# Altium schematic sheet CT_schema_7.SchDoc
size 277 x 170 mm
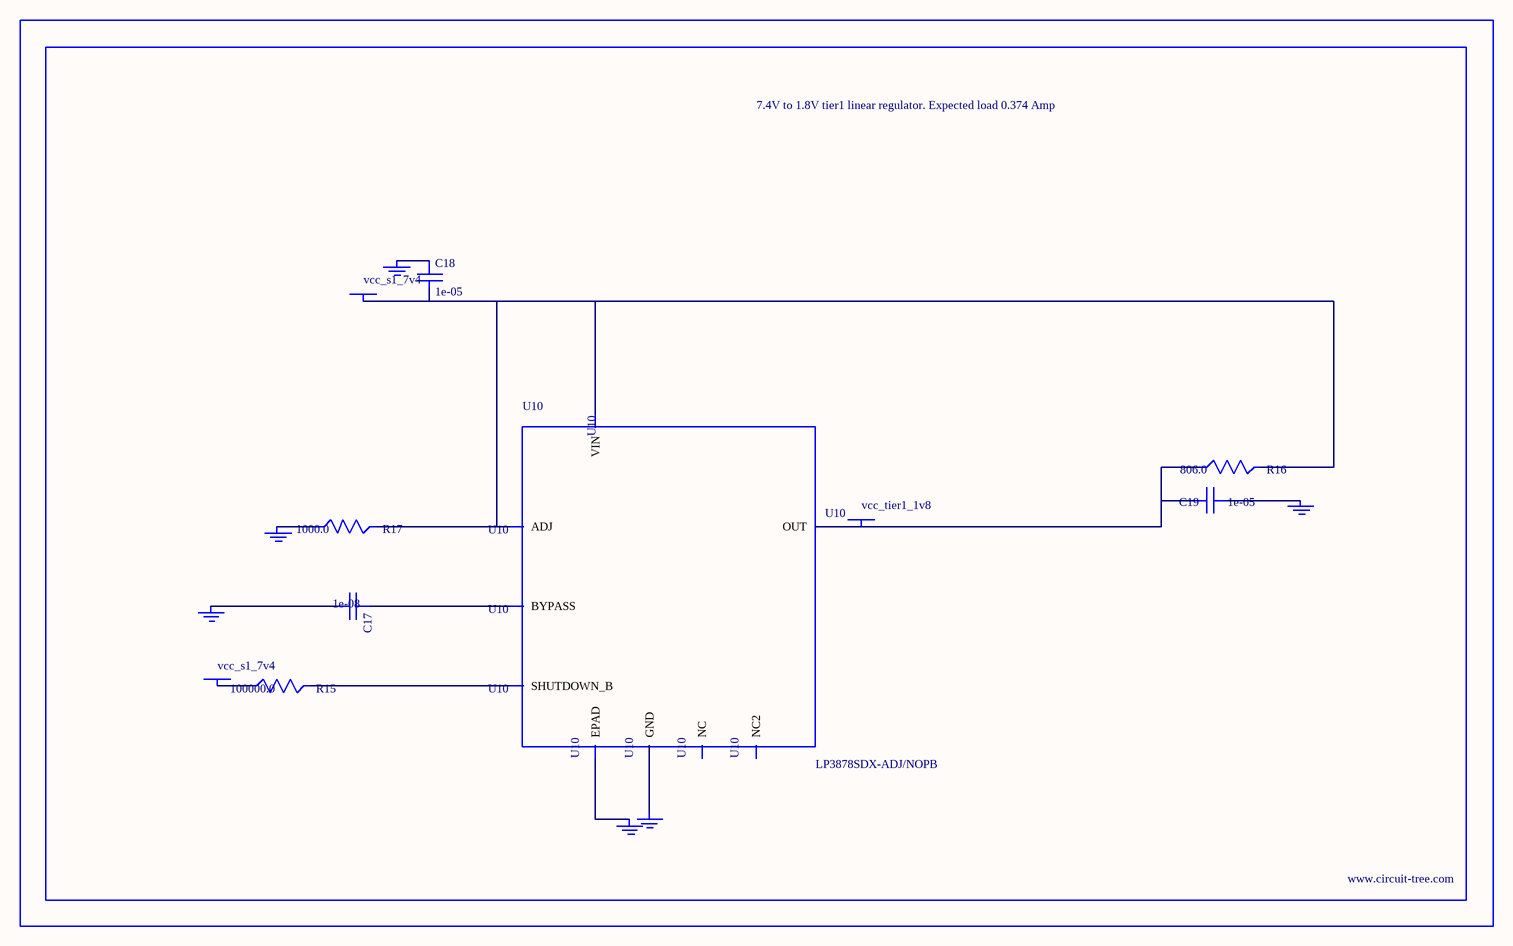
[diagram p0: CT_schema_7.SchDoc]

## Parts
BORDER6  (no value)
C17  1e-08  [C0402]
C18  1e-05  [C1206]
C19  1e-05  [C0805]
GND_INSTANCE_6_0  (no value)
GND_INSTANCE_6_1  (no value)
GND_INSTANCE_6_2  (no value)
GND_INSTANCE_6_3  (no value)
GND_INSTANCE_6_4  (no value)
GND_INSTANCE_6_5  (no value)
POWER_INSTANCE_6_0  vcc_s1_7v4
POWER_INSTANCE_6_1  vcc_s1_7v4
POWER_INSTANCE_6_2  vcc_tier1_1v8
R15  100000.0  [R0603]
R16  806.0  [R0603]
R17  1000.0  [R0603]
U10  LP3878SDX-ADJ/NOPB  [WSON-8]

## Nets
NetC17_1: C17.1 U10.1(BYPASS)
NetC17_2: C17.2 GND_INSTANCE_6_0.0(GND)
NetC18_1: C18.1 GND_INSTANCE_6_1.0(GND)
NetC18_2: C18.2 POWER_INSTANCE_6_0.0(PWR) R16.2 R17.2 U10.4(VIN) U10.6(ADJ)
NetC19_1: C19.1 GND_INSTANCE_6_2.0(GND)
NetC19_2: C19.2 POWER_INSTANCE_6_2.0(PWR) R16.1 U10.5(OUT)
NetGND_INSTANCE_6_3_0: GND_INSTANCE_6_3.0(GND) R17.1
NetGND_INSTANCE_6_4_0: GND_INSTANCE_6_4.0(GND) U10.PAD(EPAD)
NetGND_INSTANCE_6_5_0: GND_INSTANCE_6_5.0(GND) U10.3(GND)
NetPOWER_INSTANCE_6_1_0: POWER_INSTANCE_6_1.0(PWR) R15.1
NetR15_2: R15.2 U10.8(SHUTDOWN_B)

Not connected (* = marked no-connect by the designer): U10 2(NC) 7(NC2)

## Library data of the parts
BORDER6 = BORDER_PAGE6
C17 = C0402C103K3RAC
C18 = C1206C106K3RACTU
C19 = GRM219R60J106ME19D
GND_INSTANCE_6_0-GND_INSTANCE_6_5 = GND
POWER_INSTANCE_6_0-POWER_INSTANCE_6_2 = PWR
R15 = RC0603JR-07100KL
R16 = ERJ-3EKF8060V
R17 = RC0603JR-071KL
